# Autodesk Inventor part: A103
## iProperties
Shininess: 64.0
Length Units: 11272
Angle Units: 11279
Time Units: 11290
Mass Units: 11286
Length Display Precision: 3
Compacted: True
Part Number: A103
Document SubType Name: Modeling
Created: 2002-11
Designer: E. MOSS
Project: EVC
Description: HANDLE
Authority: MS. TEACHER
Density: 0.0
Volumn: 0.0
Area: 0.0
PropertySet Name: Model Information
Control State: 0
Master: False
Checked Out: False
Author: E. MOSS
Revision Number: A
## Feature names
1. Revolution1
2. Fillet1
